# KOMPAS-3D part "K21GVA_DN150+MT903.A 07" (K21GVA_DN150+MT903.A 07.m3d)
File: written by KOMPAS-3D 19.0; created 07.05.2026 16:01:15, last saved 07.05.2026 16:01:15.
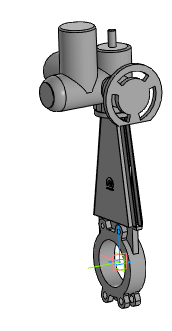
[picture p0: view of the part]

Document properties: Автор: Энергия; Полное имя файла: ..\K21GVA_DN50-DN1000+MT903.A\K21GVA_DN150+MT903.A 07.a3d

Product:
- Part/product: K21GVA_DN150+MT903.A 07
    Масса: 82.4365

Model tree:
1. Операция без истории:1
